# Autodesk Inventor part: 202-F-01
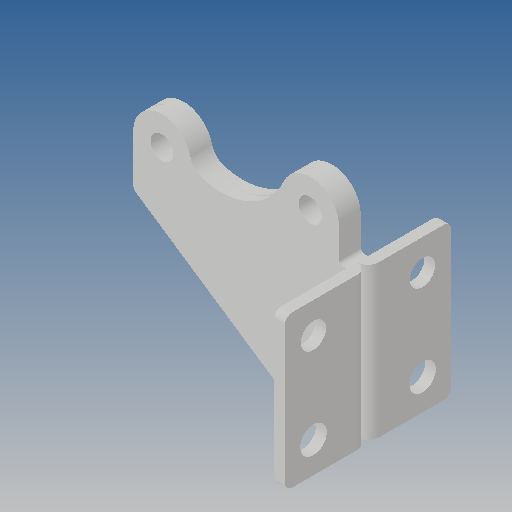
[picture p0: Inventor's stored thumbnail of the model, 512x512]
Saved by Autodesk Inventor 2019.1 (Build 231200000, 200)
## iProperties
Created: 2012-09
Part Number: 202-F-01
Material: Ogólny
Document SubType Name: Modeling
Designer: CADENGINEERING4
Density: 1 g/cm^3
Appearance: Domyślna
Author: CADENGINEERING4
Revision Number: ÈÎºÎ
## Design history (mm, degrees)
feature "Ô²½Ç1"
feature "¾µÏò1"
node "Bryła1"
node "Bryła2"
